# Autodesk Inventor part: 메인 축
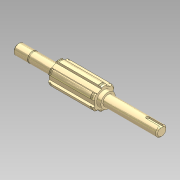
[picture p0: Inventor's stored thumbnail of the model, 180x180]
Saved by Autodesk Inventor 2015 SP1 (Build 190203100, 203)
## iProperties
Company: 한국ATC센터
Created: 2014-07
Part Number: 메인 축
Document SubType Name: 모델링
Designer: KYOUNG IL JANG
Mass: 168.352 g
Surface Area: 72.5104 cm^2
Volume: 21.4461 cm^3
Density: 7.85 g/cm^3
Material: 강철, 연강
Appearance: 반연마
변환 표준: STEP AP214IS
파일 이름: C:\Users\SeoGD\Desktop\?쒗뿕\硫붿씤 異?.stp
전처리기: Build: 253, Release: 2010 SP1 - Date: Wed 07/29/2009
전송 단위: 밀리미터
불확실성: 0.01
Author: KYOUNG IL JANG
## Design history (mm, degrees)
sketch "스케치1"
  geometry: L1 (-69.5, 0)-(69.5, 0); L2 (69.5, 0)-(69.5, 5); L3 (69.5, 5)-(55.5, 5); L4 (55.5, 5)-(55.5, 4.8); L5 (55.5, 4.8)-(54.35, 4.8); L6 (54.35, 4.8)-(54.35, 5); L7 (54.35, 5)-(30.5, 5); L8 (30.5, 5)-(30.5, 9); L9 (30.5, 9)-(-13.5, 9); L10 (-13.5, 9)-(-13.5, 7); L11 (-13.5, 7)-(-17.5, 7); L12 (-17.5, 7)-(-17.5, 5); L13 (-17.5, 5)-(-69.5, 5); L14 (-69.5, 5)-(-69.5, 0); 2 further points
  constraints: 28 end point, 9 parallel, 4 collinear, 2 perpendicular, 1 coincident, 1 horizontal, 1 midpoint
  dimensions: "d2" = 1.15 distance between parallel lines of L6 L4; "d3" = 10 diameter of L3 L1; "d4" = 9.6 diameter of L5 L1; "d6" = 44 distance between parallel lines of L10 L8; "d7" = 4 distance between parallel lines of L12 L10; "d8" = 14 diameter of L11 L1; "d9" = 18 diameter of L9 L1; "d33" = 52 distance from line of L12.end L14; "d37" = 39 distance between parallel lines of L8 L2; "d38" = 14 distance between parallel lines of L2 L4
revolve "회전1" sketch "스케치1" stored, may be unused: angle "d10" = 90 deg
sketch "스케치2"
  geometry: L1 (2.5, 10.712)-(2.5, 8.646); L2 (-2.5, 10.712)-(-2.5, 8.646); A1 r 9 centre (0, 0) between (2.5, 8.646) and (-2.5, 8.646) reference; A2 r 11 centre (0, 0) between (2.5, 10.712) and (-2.5, 10.712); 1 further point
  constraints: 4 end point, 4 point on circle, 2 parallel, 1 centre point, 1 coincident, 1 vertical
  dimensions: "d11" = 22 diameter of A2; "d12" = 5 distance between parallel lines of L1 L2
extrude "돌출1" join sketch "스케치2" stored distance "d13" = 10; taper "d14" = 0 deg
chamfer "모따기1" distance "d15" = 1; stored, may be unused: second distance "d16" = 2, angle "d17" = 45 deg
node "작업 평면1"
node "작업 평면2"
sketch "스케치3"
  geometry: L1 (2.5, 10.712)-(2.5, 10.198); L2 (-2.5, 10.712)-(-2.5, 10.198); A1 r 11 centre (0, 0) between (2.5, 10.712) and (-2.5, 10.712) reference; A2 r 10.5 centre (0, 0) between (2.5, 10.198) and (-2.5, 10.198); 1 further point
  constraints: 4 end point, 2 point on circle, 1 centre point, 1 coincident, 1 parallel, 1 vertical
  dimensions: "d19" = 21 diameter of A2
extrude "돌출2" cut sketch "스케치3" distance "d20" = 1.35; taper "d21" = 0 deg
node "작업 평면3"
sketch "스케치4"
  geometry: L1 (-26, -5)-(-26, 5) reference; L2 (-26, 1.5)-(-12.5, 1.5); L3 (-12.5, -1.5)-(-26, -1.5); A1 r 1.5 centre (-12.5, 0) between (-12.5, -1.5) and (-12.5, 1.5); 2 further points
  constraints: 4 end point, 2 perpendicular, 2 point on circle, 2 point on line, 2 tangent, 1 centre point, 1 horizontal alignment, 1 midpoint
  dimensions: "d25" = 3 distance between parallel lines of L3 L2; "d26" = 15 dimension on A1 L1
extrude "돌출3" cut sketch "스케치4" distance "d27" = 1.8; taper "d28" = 0 deg
chamfer "모따기2" distance "d29" = 1; stored, may be unused: second distance "d30" = 2, angle "d31" = 45 deg
node "솔리드1"
node "솔리드 본체"
node "곡면 본체"
mirror "대칭1"
pattern_circular "원형 패턴1" dims "d23" = 360 deg
node "솔리드2"
other parameters: "d18" = -1.65
